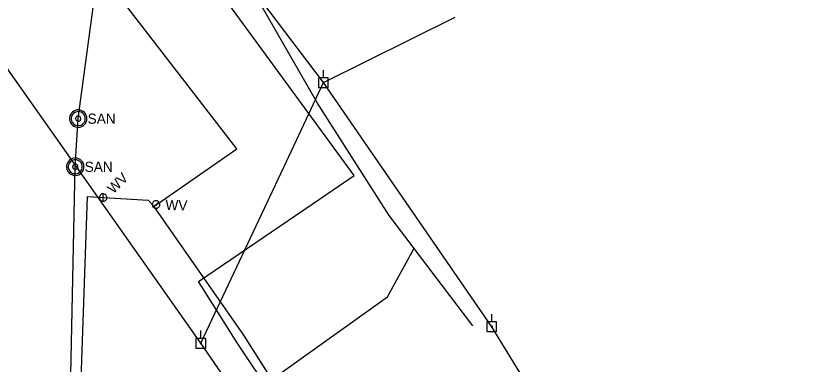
# Model space of a CAD drawing. Extents: x 596028 to 606371, y 330010 to 403088.
# Drawn here: x 596450.8 to 596751.9, y 343207.1 to 343338.5 of the extents above; entities that cross this region are included whole.
import ezdxf

# ---------------------------------------------------------------- set-up
doc = ezdxf.new("R2010")
doc.units = 0
for name, color, linetype in [('E_UTL_EPowerPole', 7, 'Continuous'), ('E_UTL_FO_UG', 7, 'Continuous'), ('E_UTL_G_UG', 7, 'Continuous'), ('E_UTL_Overhead', 7, 'Continuous'), ('E_UTL_SAN_MH', 7, 'Continuous'), ('E_UTL_SAN_UG', 7, 'Continuous'), ('E_UTL_W', 7, 'Continuous'), ('E_UTL_W_UG', 7, 'Continuous')]:
    doc.layers.add(name, color=color, linetype=linetype)

msp = doc.modelspace()

# ---------------------------------------------------------------- linework, layer by layer
at = {"layer": 'E_UTL_EPowerPole'}
for points in [[(596568.63, 343315.14), (596564.94, 343315.14)], [(596564.94, 343315.14), (596564.94, 343311.44)], [(596566.79, 343315.14), (596566.79, 343318.04)], [(596568.63, 343311.44), (596568.63, 343315.14)], [(596567.06, 343313.29), (596567.05, 343313.34), (596567.04, 343313.38), (596567.02, 343313.42), (596566.99, 343313.46), (596566.96, 343313.49), (596566.92, 343313.51), (596566.87, 343313.52), (596566.83, 343313.53), (596566.78, 343313.53), (596566.74, 343313.52), (596566.7, 343313.5), (596566.66, 343313.47), (596566.63, 343313.44), (596566.61, 343313.4), (596566.59, 343313.36), (596566.58, 343313.32), (596566.58, 343313.27), (596566.59, 343313.23), (596566.61, 343313.18), (596566.63, 343313.15), (596566.66, 343313.11), (596566.7, 343313.09), (596566.74, 343313.07), (596566.78, 343313.06), (596566.83, 343313.06), (596566.87, 343313.06), (596566.92, 343313.08), (596566.96, 343313.1), (596566.99, 343313.13), (596567.02, 343313.16), (596567.04, 343313.2), (596567.05, 343313.25), (596567.06, 343313.29)], [(596564.94, 343311.44), (596568.63, 343311.44)], [(596630.34, 343223.03), (596630.34, 343225.94)], [(596632.18, 343223.03), (596628.49, 343223.03)], [(596628.49, 343223.03), (596628.49, 343219.34)], [(596632.18, 343219.34), (596632.18, 343223.03)], [(596520.56, 343216.79), (596520.56, 343219.7)], [(596628.49, 343219.34), (596632.18, 343219.34)], [(596630.61, 343221.19), (596630.6, 343221.24), (596630.59, 343221.28), (596630.57, 343221.32), (596630.54, 343221.36), (596630.51, 343221.39), (596630.47, 343221.41), (596630.43, 343221.42), (596630.38, 343221.43), (596630.34, 343221.43), (596630.29, 343221.42), (596630.25, 343221.4), (596630.21, 343221.37), (596630.18, 343221.34), (596630.16, 343221.3), (596630.14, 343221.26), (596630.13, 343221.21), (596630.13, 343221.17), (596630.14, 343221.12), (596630.16, 343221.08), (596630.18, 343221.04), (596630.21, 343221.01), (596630.25, 343220.98), (596630.29, 343220.97), (596630.34, 343220.96), (596630.38, 343220.95), (596630.43, 343220.96), (596630.47, 343220.97), (596630.51, 343221), (596630.54, 343221.03), (596630.57, 343221.06), (596630.59, 343221.1), (596630.6, 343221.15), (596630.61, 343221.19)], [(596522.41, 343216.79), (596518.72, 343216.79)], [(596518.72, 343216.79), (596518.72, 343213.1)], [(596522.41, 343213.1), (596522.41, 343216.79)], [(596518.72, 343213.1), (596522.41, 343213.1)], [(596520.83, 343214.94), (596520.83, 343214.99), (596520.82, 343215.03), (596520.79, 343215.07), (596520.77, 343215.11), (596520.73, 343215.14), (596520.69, 343215.16), (596520.65, 343215.18), (596520.61, 343215.18), (596520.56, 343215.18), (596520.52, 343215.17), (596520.47, 343215.15), (596520.44, 343215.12), (596520.41, 343215.09), (596520.38, 343215.05), (596520.37, 343215.01), (596520.36, 343214.97), (596520.36, 343214.92), (596520.37, 343214.88), (596520.38, 343214.83), (596520.41, 343214.8), (596520.44, 343214.76), (596520.47, 343214.74), (596520.52, 343214.72), (596520.56, 343214.71), (596520.61, 343214.71), (596520.65, 343214.71), (596520.69, 343214.73), (596520.73, 343214.75), (596520.77, 343214.78), (596520.79, 343214.82), (596520.82, 343214.86), (596520.83, 343214.9), (596520.83, 343214.94)]]:
    msp.add_lwpolyline(points, dxfattribs=at)
at = {"layer": 'E_UTL_FO_UG'}
for points in [[(596623.2, 343221.5), (596591.63, 343263.11), (596564.61, 343305.57), (596536.54, 343354.45), (596533.7, 343373.6), (596535.42, 343430.17), (596534.15, 343442.91), (596537.51, 343537.7), (596537.51, 343588.84), (596540.54, 343656.31), (596541, 343722.96), (596544.11, 343796.55), (596541.22, 343839.02), (596528.82, 343853.36)], [(596494.16, 343163.21), (596590.93, 343232.42), (596600.94, 343250.54)]]:
    msp.add_lwpolyline(points, dxfattribs=at)
at = {"layer": 'E_UTL_G_UG'}
msp.add_line((596519.65, 343238.25), (596562.55, 343267.45), dxfattribs=at)
for points in [[(596562.55, 343267.45), (596578.45, 343278.27), (596527.67, 343347.67)], [(596748.84, 342824.86), (596703.98, 342914.39), (596661.09, 342996.89), (596652.32, 343013.67), (596618.19, 343079.39), (596590.3, 343127.42), (596559.75, 343176.73), (596547.17, 343195.7), (596534.58, 343214.66), (596519.65, 343238.25)]]:
    msp.add_lwpolyline(points, dxfattribs=at)
at = {"layer": 'E_UTL_Overhead'}
for p, q in [((596566.82, 343313.29), (596616.49, 343337.98)), ((596552.85, 343283.57), (596566.82, 343313.29)), ((596520.59, 343214.94), (596552.85, 343283.57)), ((596677.75, 343143.58), (596630.37, 343221.19))]:
    msp.add_line(p, q, dxfattribs=at)
for points in [[(596907.13, 342499.57), (596872.87, 342572.96), (596807.17, 342701.41), (596752.6, 342808.68), (596696.55, 342921.05), (596669.38, 342971.18), (596598.89, 343101.31), (596520.59, 343214.94), (596433.09, 343338.93), (596392.19, 343473.17), (596318.24, 343551.79), (596215.53, 343658.6), (596116.41, 343762.49), (596042.62, 343840.48)], [(596630.37, 343221.19), (596566.82, 343313.29), (596534.56, 343356.08)]]:
    msp.add_lwpolyline(points, dxfattribs=at)
at = {"layer": 'E_UTL_SAN_MH'}
for points in [[(596477.59, 343299.7), (596477.53, 343300.33), (596477.35, 343300.93), (596477.07, 343301.49), (596476.68, 343301.98), (596476.2, 343302.39), (596475.66, 343302.71), (596475.07, 343302.91), (596474.45, 343303), (596473.82, 343302.97), (596473.21, 343302.82), (596472.64, 343302.56), (596472.13, 343302.2), (596471.7, 343301.74), (596471.36, 343301.22), (596471.12, 343300.63), (596471, 343300.02), (596471, 343299.39), (596471.12, 343298.78), (596471.36, 343298.19), (596471.7, 343297.66), (596472.13, 343297.21), (596472.64, 343296.85), (596473.21, 343296.59), (596473.82, 343296.44), (596474.45, 343296.41), (596475.07, 343296.5), (596475.66, 343296.7), (596476.2, 343297.02), (596476.68, 343297.43), (596477.07, 343297.92), (596477.35, 343298.48), (596477.53, 343299.08), (596477.59, 343299.7)], [(596476.93, 343299.7), (596476.88, 343300.2), (596476.74, 343300.69), (596476.51, 343301.13), (596476.2, 343301.53), (596475.82, 343301.86), (596475.39, 343302.11), (596474.91, 343302.27), (596474.42, 343302.34), (596473.91, 343302.32), (596473.43, 343302.2), (596472.97, 343301.99), (596472.56, 343301.7), (596472.21, 343301.34), (596471.94, 343300.91), (596471.76, 343300.45), (596471.66, 343299.96), (596471.66, 343299.45), (596471.76, 343298.96), (596471.94, 343298.5), (596472.21, 343298.07), (596472.56, 343297.71), (596472.97, 343297.42), (596473.43, 343297.21), (596473.91, 343297.09), (596474.42, 343297.07), (596474.91, 343297.14), (596475.39, 343297.3), (596475.82, 343297.55), (596476.2, 343297.88), (596476.51, 343298.28), (596476.74, 343298.72), (596476.88, 343299.21), (596476.93, 343299.7)], [(596475.28, 343299.7), (596475.26, 343299.89), (596475.21, 343300.07), (596475.12, 343300.24), (596475.01, 343300.39), (596474.86, 343300.51), (596474.7, 343300.61), (596474.52, 343300.67), (596474.34, 343300.69), (596474.15, 343300.68), (596473.97, 343300.64), (596473.8, 343300.56), (596473.64, 343300.45), (596473.51, 343300.32), (596473.41, 343300.16), (596473.34, 343299.98), (596473.3, 343299.8), (596473.3, 343299.61), (596473.34, 343299.43), (596473.41, 343299.25), (596473.51, 343299.09), (596473.64, 343298.96), (596473.8, 343298.85), (596473.97, 343298.77), (596474.15, 343298.72), (596474.34, 343298.72), (596474.52, 343298.74), (596474.7, 343298.8), (596474.86, 343298.9), (596475.01, 343299.02), (596475.12, 343299.17), (596475.21, 343299.34), (596475.26, 343299.52), (596475.28, 343299.7)], [(596476.47, 343281.55), (596476.41, 343282.18), (596476.23, 343282.78), (596475.94, 343283.34), (596475.55, 343283.83), (596475.08, 343284.24), (596474.54, 343284.56), (596473.94, 343284.76), (596473.32, 343284.85), (596472.7, 343284.82), (596472.09, 343284.67), (596471.52, 343284.41), (596471, 343284.05), (596470.57, 343283.59), (596470.23, 343283.07), (596470, 343282.48), (596469.88, 343281.87), (596469.88, 343281.24), (596470, 343280.63), (596470.23, 343280.04), (596470.57, 343279.51), (596471, 343279.06), (596471.52, 343278.7), (596472.09, 343278.44), (596472.7, 343278.29), (596473.32, 343278.26), (596473.94, 343278.35), (596474.54, 343278.55), (596475.08, 343278.87), (596475.55, 343279.28), (596475.94, 343279.77), (596476.23, 343280.33), (596476.41, 343280.93), (596476.47, 343281.55)], [(596475.81, 343281.55), (596475.76, 343282.05), (596475.62, 343282.54), (596475.39, 343282.98), (596475.08, 343283.38), (596474.7, 343283.71), (596474.26, 343283.96), (596473.79, 343284.12), (596473.29, 343284.19), (596472.79, 343284.17), (596472.3, 343284.05), (596471.85, 343283.84), (596471.44, 343283.55), (596471.09, 343283.19), (596470.82, 343282.76), (596470.63, 343282.3), (596470.54, 343281.81), (596470.54, 343281.3), (596470.63, 343280.81), (596470.82, 343280.35), (596471.09, 343279.92), (596471.44, 343279.56), (596471.85, 343279.27), (596472.3, 343279.06), (596472.79, 343278.94), (596473.29, 343278.92), (596473.79, 343278.99), (596474.26, 343279.15), (596474.7, 343279.4), (596475.08, 343279.73), (596475.39, 343280.13), (596475.62, 343280.57), (596475.76, 343281.06), (596475.81, 343281.55)], [(596474.16, 343281.55), (596474.14, 343281.74), (596474.09, 343281.92), (596474, 343282.09), (596473.88, 343282.24), (596473.74, 343282.36), (596473.58, 343282.46), (596473.4, 343282.52), (596473.21, 343282.54), (596473.03, 343282.53), (596472.84, 343282.49), (596472.67, 343282.41), (596472.52, 343282.3), (596472.39, 343282.17), (596472.29, 343282.01), (596472.22, 343281.83), (596472.18, 343281.65), (596472.18, 343281.46), (596472.22, 343281.28), (596472.29, 343281.1), (596472.39, 343280.94), (596472.52, 343280.81), (596472.67, 343280.7), (596472.84, 343280.62), (596473.03, 343280.57), (596473.21, 343280.57), (596473.4, 343280.59), (596473.58, 343280.65), (596473.74, 343280.75), (596473.88, 343280.87), (596474, 343281.02), (596474.09, 343281.19), (596474.14, 343281.37), (596474.16, 343281.55)]]:
    msp.add_lwpolyline(points, dxfattribs=at)
at = {"layer": 'E_UTL_SAN_UG'}
for points in [[(596474.29, 343299.7), (596483.68, 343369.67), (596488.27, 343570.99), (596492.83, 343728.76), (596493.38, 343805.11), (596496.8, 343910.62), (596505.55, 344309.74)], [(596466.66, 342967.7), (596473.17, 343281.55), (596474.29, 343299.7)]]:
    msp.add_lwpolyline(points, dxfattribs=at)
at = {"layer": 'E_UTL_W'}
for points in [[(596484.71, 343270.95), (596484.51, 343271.12), (596484.27, 343271.25), (596484.01, 343271.34), (596483.74, 343271.37), (596483.47, 343271.35), (596483.21, 343271.28), (596482.96, 343271.16), (596482.75, 343271), (596482.56, 343270.8), (596482.42, 343270.57), (596482.33, 343270.31), (596482.28, 343270.04), (596482.29, 343269.77), (596482.35, 343269.51), (596482.45, 343269.26), (596482.61, 343269.03), (596482.8, 343268.84), (596483.02, 343268.69), (596483.27, 343268.58), (596483.54, 343268.53), (596483.81, 343268.52), (596484.08, 343268.56), (596484.33, 343268.66), (596484.56, 343268.8), (596484.76, 343268.98), (596484.92, 343269.2), (596485.04, 343269.44), (596485.11, 343269.71), (596485.13, 343269.98), (596485.1, 343270.25), (596485.02, 343270.5), (596484.89, 343270.74), (596484.71, 343270.95)], [(596483.71, 343268.52), (596483.71, 343271.37)], [(596505.08, 343267.25), (596505.06, 343267.52), (596504.99, 343267.78), (596504.87, 343268.03), (596504.71, 343268.25), (596504.51, 343268.43), (596504.28, 343268.57), (596504.03, 343268.67), (596503.76, 343268.72), (596503.49, 343268.71), (596503.23, 343268.66), (596502.98, 343268.55), (596502.75, 343268.4), (596502.56, 343268.21), (596502.4, 343267.99), (596502.3, 343267.74), (596502.24, 343267.48), (596502.23, 343267.21), (596502.27, 343266.94), (596502.36, 343266.68), (596502.5, 343266.45), (596502.68, 343266.25), (596502.9, 343266.08), (596503.14, 343265.96), (596503.4, 343265.89), (596503.67, 343265.87), (596503.94, 343265.9), (596504.2, 343265.98), (596504.44, 343266.11), (596504.65, 343266.28), (596504.82, 343266.49), (596504.96, 343266.72), (596505.04, 343266.98), (596505.08, 343267.25)], [(596502.61, 343266.32), (596504.69, 343268.27)]]:
    msp.add_lwpolyline(points, dxfattribs=at)
at = {"layer": 'E_UTL_W_UG'}
for points in [[(596502.84, 343266.57), (596534.18, 343288.36), (596475.61, 343364.22), (596483.72, 343742), (596509.64, 343741.09)], [(596474.44, 343172.22), (596477.81, 343270.29), (596500.69, 343268.96), (596502.86, 343266.64)], [(596627.29, 343069.3), (596580.15, 343149.5), (596536.84, 343217.98), (596502.86, 343266.64)]]:
    msp.add_lwpolyline(points, dxfattribs=at)

# ---------------------------------------------------------------- texts
at = {"layer": 'E_UTL_SAN_MH'}
for p in [(596477.85, 343297.76), (596476.73, 343279.61)]:
    msp.add_text('SAN', height=3.849, dxfattribs=at).set_placement(p)
at = {"layer": 'E_UTL_W'}
for rotation, p in [(45, (596487.59, 343271.1)), (358.158, (596507.15, 343265.26))]:
    msp.add_text('WV', height=3.85, rotation=rotation, dxfattribs=at).set_placement(p)

doc.saveas('drawing.dxf')
